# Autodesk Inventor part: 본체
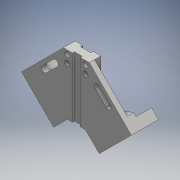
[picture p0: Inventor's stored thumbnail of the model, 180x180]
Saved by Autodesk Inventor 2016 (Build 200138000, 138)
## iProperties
Created: 2019-04
Part Number: 본체
Material: 일반
Document SubType Name: Modeling
Designer: 605-06
Density: 1 g/cm^3
Appearance: 기본값
Author: 605-06
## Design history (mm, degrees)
sketch "스케치1"
  geometry: L1 (84.853, -24.33)-(35.355, -73.827); L2 (20, 40.523)-(84.853, -24.33); L3 (0, -109.183)-(0, 60.523); L4 (35.355, -73.827)-(15.47, -53.941); L5 (11.934, -52.477)-(0, -52.477); L6 (20, 40.523)-(0, 40.523); A1 r 5 centre (11.934, -57.477) between (15.47, -53.941) and (11.934, -52.477); 2 further points
  constraints: 12 end point, 5 point on line, 2 perpendicular, 2 point on circle, 2 tangent, 1 centre point, 1 vertical
  dimensions: "d1" = 90 deg angle of L2 L1; "d4" = 120 distance of L1.start L3.start; "d5" = 120 distance of L3.end L1.start; "d6" = 50 distance of L1.end L3.start; "d7" = 40 diameter of L2.start L3; "d8" = 45 deg angle of L3 L1; "d9" = 93 distance between parallel lines of L5 L6; "d10" = 90 deg angle of L4 L1; "d49" = 5 radius of A1
extrude "돌출1" new body sketch "스케치1" distance "d11" = 18; taper "d12" = 0 deg
sketch "스케치2"
  geometry: L1 (-15.47, 53.941)-(-35.355, 73.827) reference; L2 (-84.853, 24.33)-(-20, -40.523) reference; L3 (-74.246, 13.723)-(-24.749, 63.221); L4 (-84.853, 24.33)-(-35.355, 73.827) reference; 2 further points
  constraints: 2 end point, 2 point on line, 1 perpendicular
  dimensions: "d14" = 15 distance between parallel lines of L4 L3
extrude "돌출2" join sketch "스케치2" distance "d15" = 24; taper "d16" = 0 deg
sketch "스케치3"
  geometry: L1 (-74.246, 13.723)-(-20, -40.523) reference; L2 (-70.711, 10.188)-(-52.429, 16.281); L3 (-47.312, 15.074)-(-21.464, -10.774); L4 (-20, -14.31)-(-20, -40.523); L5 (-35.355, 73.827)-(-84.853, 24.33) reference; L6 (-49.497, 3.117)-(-32.527, -13.854); L7 (-49.497, 3.117)-(-32.527, -13.854); L8 (-52.679, -0.065)-(-35.709, -17.036); L9 (-29.345, -10.672)-(-46.315, 6.299); A1 r 4.5 centre (-49.497, 3.117) between (-46.315, 6.299) and (-52.679, -0.065); A2 r 4.5 centre (-32.527, -13.854) between (-35.709, -17.036) and (-29.345, -10.672); A3 r 5 centre (-50.848, 11.538) between (-47.312, 15.074) and (-52.429, 16.281); A4 r 5 centre (-25, -14.31) between (-20, -14.31) and (-21.464, -10.774); 3 further points
  constraints: 16 end point, 8 point on circle, 8 tangent, 4 centre point, 3 parallel, 3 point on line, 1 collinear, 1 midpoint, 1 vertical
  dimensions: "d17" = 20 distance between parallel lines of L3 L1; "d18" = 20 distance from line of L2.start L5; "d19" = 30 distance from line of point (-49.497, 17.259) L5; "d20" = 9 diameter of A2; "d21" = 24 distance of L6.start L6.end; "d22" = 40 distance from line of L5 L6.start; "d23" = 10 distance between parallel lines of L6 L1; "d24" = 5 radius of A3; "d25" = 5 radius of A4
extrude "돌출3" cut sketch "스케치3" distance "d26" = 10; taper "d27" = 0 deg
extrude "돌출4" cut sketch "스케치3" stored distance "d28" = 10; taper "d29" = 0 deg
sketch "스케치5"
  geometry: L1 (0, -52.477)-(0, 40.523) reference; L2 (0, 40.523)-(-20, 40.523) reference; 3 further points
  constraints: 1 vertical alignment
  dimensions: "d33" = 14 distance from line of L1 point (-14, 34.523); "d34" = 6 distance from line of L2 point (-14, 34.523); "d35" = 12 distance of point (-14, 34.523) point (-14, 22.523)
hole "구멍1" sketch "스케치5" at (-14, 34.523), (-14, 22.523) diameter "d36" = 4.5; stored, may be unused: countersink angle "d40" = 90 deg, drill point angle "d42" = 118 deg; dims "d37" = 6, "d38" = 8, "d39" = 10, "d41" = 8
sketch "스케치6"
  geometry: L1 (-11.934, 52.477)-(0, 52.477) reference; L2 (-8, 52.477)-(-8, -40.523); L3 (-20, -40.523)-(0, -40.523) reference; L4 (0, -40.523)-(0, 52.477) reference; 2 further points
  constraints: 2 end point, 2 point on line, 1 vertical
  dimensions: "d43" = 8 distance between parallel lines of L4 L2
extrude "돌출5" cut sketch "스케치6" distance "d44" = 3.5; taper "d45" = 0 deg
sketch "스케치7"
  geometry: L1 (0, 40.523)-(-20, 40.523) reference; L2 (-6, 40.523)-(-6, -52.477); L3 (-8, -52.477)-(0, -52.477) reference; L4 (0, -52.477)-(0, 40.523) reference; 1 further point
  constraints: 2 end point, 2 point on line, 1 vertical
  dimensions: "d46" = 6 distance between parallel lines of L4 L2
extrude "돌출6" cut sketch "스케치7" distance "d47" = 3; taper "d48" = 0 deg
node "솔리드1"
mirror "대칭3"
